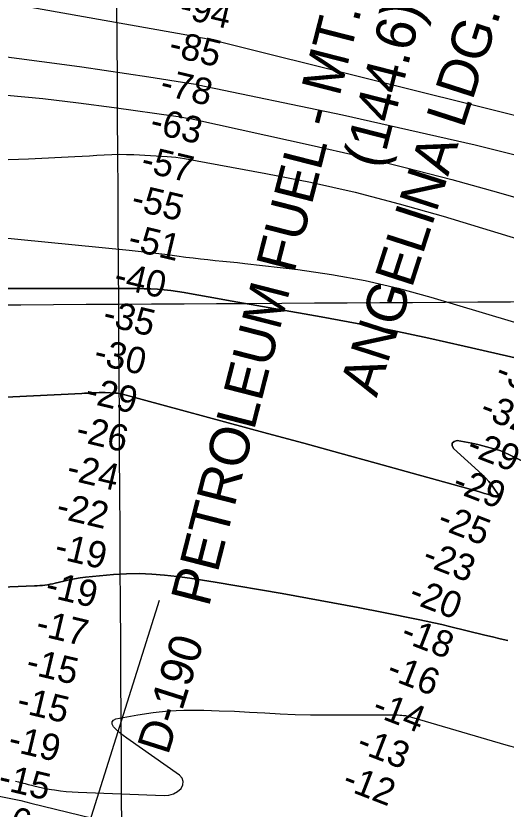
# Model space of a CAD drawing. Extents: x 3477039 to 3515015, y 546746 to 572297.
# Drawn here: x 3496761 to 3497998, y 563045 to 565048 of the extents above; entities that cross this region are included whole.
import ezdxf

# ---------------------------------------------------------------- set-up
doc = ezdxf.new("R2010")
doc.units = 0
for name, color, linetype in [('V-CHAN-NAID', 7, 'Continuous'), ('V-GRID-MAJR', 7, 'Continuous'), ('V-RIVR-RANG', 7, 'Continuous'), ('V-RIVR-RANG-IDEN', 7, 'Continuous'), ('V-TOPO-DPTH', 7, 'Continuous'), ('V-TOPO-GNAM-IDEN', 7, 'Continuous'), ('V-TOPO-MAJR', 7, 'Continuous'), ('V-TOPO-MINR', 7, 'Continuous')]:
    doc.layers.add(name, color=color, linetype=linetype)

msp = doc.modelspace()

# ---------------------------------------------------------------- linework, layer by layer
at = {"layer": 'V-GRID-MAJR'}
for points in [[(3497073.037565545, 555496.0515890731), (3497056.56, 558259.177), (3497020.416, 564320.132), (3496984.272, 570381.104), (3496984.251, 570384.554)], [(3481202.017, 564229.252), (3486474.821, 564258.778), (3491747.6210000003, 564289.072), (3497020.416, 564320.132), (3502293.207, 564351.96), (3507565.9930000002, 564384.554), (3512838.775, 564417.915)]]:
    msp.add_spline(points, degree=3, dxfattribs=at)
at = {"layer": 'V-RIVR-RANG'}
msp.add_line((3496858.6666, 562733.698), (3497123.1673, 563573.0069000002), dxfattribs=at)
at = {"layer": 'V-TOPO-DPTH'}
for points in [[(3496702.2082517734, 564359.3917912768), (3496786.063740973, 564359.4427881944), (3496869.919228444, 564359.4967588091), (3497051.3101174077, 564359.6183290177), (3497068.1567175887, 564359.4691649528), (3497084.996673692, 564359.1062361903), (3497101.8266636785, 564358.4226603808), (3497118.6500095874, 564357.5253198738), (3497135.4320060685, 564356.170667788), (3497152.1656604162, 564354.4213604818), (3497168.8268015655, 564352.0800703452), (3497185.4396005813, 564349.3441249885), (3497199.1042991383, 564346.8440532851), (3497222.5170422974, 564342.5832363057), (3497245.9350614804, 564338.351775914), (3497269.3609946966, 564334.1643504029), (3497292.7922039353, 564330.0062814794), (3497531.493061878, 564287.8781829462), (3497622.125860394, 564271.1326110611), (3497712.5617484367, 564253.4225573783), (3497802.7022707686, 564234.265780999), (3497892.645882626, 564214.1445228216), (3498028.15102787, 564182.6885954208)], [(3498028.15102787, 564182.6885954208), (3497892.645882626, 564214.1445228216), (3497802.7022707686, 564234.265780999), (3497712.5617484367, 564253.4225573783), (3497622.125860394, 564271.1326110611), (3497531.493061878, 564287.8781829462), (3497292.7922039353, 564330.0062814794), (3497269.3609946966, 564334.1643504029), (3497245.9350614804, 564338.351775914), (3497222.5170422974, 564342.5832363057), (3497199.1042991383, 564346.8440532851), (3497185.4396005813, 564349.3441249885), (3497168.8268015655, 564352.0800703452), (3497152.1656604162, 564354.4213604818), (3497135.4320060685, 564356.170667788), (3497118.6500095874, 564357.5253198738), (3497101.8266636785, 564358.4226603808), (3497084.996673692, 564359.1062361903), (3497068.1567175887, 564359.4691649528), (3497051.3101174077, 564359.6183290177), (3496869.919228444, 564359.4967588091), (3496786.063740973, 564359.4427881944), (3496702.2082517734, 564359.3917912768)], [(3496682.648173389, 564083.0086380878), (3496926.9095199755, 564094.6061176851), (3496934.297223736, 564094.9736675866), (3496941.6836987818, 564095.3635357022), (3496949.068330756, 564095.7868811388), (3496956.4517340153, 564096.2325447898), (3496963.8356742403, 564096.5856461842), (3496971.2215552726, 564096.7933057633), (3496978.610347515, 564096.7828026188), (3496986.001080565, 564096.6268576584), (3497012.538516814, 564095.6746411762), (3497016.9247466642, 564095.3660759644), (3497021.280975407, 564094.8591976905), (3497025.5922024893, 564094.0548498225), (3497029.873428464, 564093.0521888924), (3497396.2161167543, 563993.8614625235), (3497487.5405047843, 563969.0158873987), (3497578.8243943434, 563944.0230949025), (3497670.047536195, 563918.8094763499), (3497761.2301795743, 563893.4486404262), (3497928.218583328, 563846.786023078), (3497935.868042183, 563844.6167320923), (3497943.5060247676, 563842.4083141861), (3497951.1267929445, 563840.1412058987), (3497958.7360848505, 563837.8349706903), (3497969.531241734, 563834.5177690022), (3497971.7475437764, 563833.9044253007), (3497973.9813136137, 563833.3753167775), (3497978.518724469, 563832.6540404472), (3497979.7706447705, 563833.034006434), (3497980.598348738, 563833.6732466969), (3497980.789728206, 563834.7013983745), (3497980.5568913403, 563835.9888243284), (3497969.17878619, 563853.1896982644), (3497962.0737511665, 563863.1009553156), (3497954.5078858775, 563872.6167491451), (3497946.2507751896, 563881.5393481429), (3497937.532834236, 563890.0664839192), (3497865.0312539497, 563955.8407342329), (3497862.2254753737, 563963.2474171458), (3497862.3658845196, 563969.2603234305), (3497866.925575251, 563973.1825647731), (3497874.431453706, 563975.7110294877), (3497893.0607242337, 563972.5935193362), (3497911.5913795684, 563969.0126805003), (3497929.974112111, 563964.7368486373), (3497948.2582294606, 563959.9976880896), (3497979.4528381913, 563951.2820016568), (3497982.36154546, 563950.3874097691), (3497985.233414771, 563949.3945763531), (3497988.0500271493, 563948.2543806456), (3497990.82980157, 563947.0159434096), (3498512.3754094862, 563698.2603883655)], [(3498512.3754094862, 563698.2603883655), (3497990.82980157, 563947.0159434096), (3497988.0500271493, 563948.2543806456), (3497985.233414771, 563949.3945763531), (3497982.36154546, 563950.3874097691), (3497979.4528381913, 563951.2820016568), (3497948.2582294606, 563959.9976880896), (3497929.974112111, 563964.7368486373), (3497911.5913795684, 563969.0126805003), (3497893.0607242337, 563972.5935193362), (3497874.431453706, 563975.7110294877), (3497866.925575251, 563973.1825647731), (3497862.3658845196, 563969.2603234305), (3497862.2254753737, 563963.2474171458), (3497865.0312539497, 563955.8407342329), (3497937.532834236, 563890.0664839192), (3497946.2507751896, 563881.5393481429), (3497954.5078858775, 563872.6167491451), (3497962.0737511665, 563863.1009553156), (3497969.17878619, 563853.1896982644), (3497980.5568913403, 563835.9888243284), (3497980.789728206, 563834.7013983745), (3497980.598348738, 563833.6732466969), (3497979.7706447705, 563833.034006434), (3497978.518724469, 563832.6540404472), (3497973.9813136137, 563833.3753167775), (3497971.7475437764, 563833.9044253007), (3497969.531241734, 563834.5177690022), (3497958.7360848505, 563837.8349706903), (3497951.1267929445, 563840.1412058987), (3497943.5060247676, 563842.4083141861), (3497935.868042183, 563844.6167320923), (3497928.218583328, 563846.786023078), (3497761.2301795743, 563893.4486404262), (3497670.047536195, 563918.8094763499), (3497578.8243943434, 563944.0230949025), (3497487.5405047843, 563969.0158873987), (3497396.2161167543, 563993.8614625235), (3497029.873428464, 564093.0521888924), (3497025.5922024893, 564094.0548498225), (3497021.280975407, 564094.8591976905), (3497016.9247466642, 564095.3660759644), (3497012.538516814, 564095.6746411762), (3496986.001080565, 564096.6268576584), (3496978.610347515, 564096.7828026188), (3496971.2215552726, 564096.7933057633), (3496963.8356742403, 564096.5856461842), (3496956.4517340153, 564096.2325447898), (3496949.068330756, 564095.7868811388), (3496941.6836987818, 564095.3635357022), (3496934.297223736, 564094.9736675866), (3496926.9095199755, 564094.6061176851), (3496682.648173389, 564083.0086380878)], [(3498002.228981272, 563471.02758094), (3497983.099634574, 563475.6016861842), (3497963.9761578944, 563480.2002711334), (3497944.85659456, 563484.8151758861), (3497855.612866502, 563506.4164557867), (3497835.861812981, 563511.0774207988), (3497816.077147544, 563515.5869153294), (3497796.242064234, 563519.8692041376), (3497776.3733690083, 563524.0000224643), (3497688.7559025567, 563541.6926317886), (3497624.999183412, 563554.2657245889), (3497561.170379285, 563566.4517011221), (3497497.233447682, 563578.0570032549), (3497433.2244310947, 563589.2751891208), (3497263.4964403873, 563618.22715432), (3497231.6693679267, 563623.3745236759), (3497199.790560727, 563628.1554442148), (3497167.8341514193, 563632.3866915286), (3497135.8260073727, 563636.2514900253), (3497103.770887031, 563638.8360883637), (3497071.70499835, 563640.0923518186), (3497039.622957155, 563639.3561129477), (3497007.5301476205, 563637.2915391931), (3496936.5476980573, 563630.5036335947), (3496922.6929846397, 563628.8677120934), (3496908.9076787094, 563626.8256128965), (3496895.2264840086, 563624.1742471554), (3496881.6146967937, 563621.1167037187), (3496860.419542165, 563615.8590361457), (3496853.932455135, 563614.3675956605), (3496847.4172268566, 563613.0257411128), (3496840.859786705, 563611.9082654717), (3496834.2742053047, 563610.9403757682), (3496827.6599558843, 563610.1740204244), (3496821.035717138, 563609.5261859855), (3496814.396494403, 563609.0561329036), (3496807.7472823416, 563608.7046007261), (3496641.274971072, 563602.1401168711)], [(3498002.228981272, 563471.02758094), (3497983.099634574, 563475.6016861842), (3497963.9761578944, 563480.2002711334), (3497944.85659456, 563484.8151758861), (3497855.612866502, 563506.4164557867), (3497835.861812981, 563511.0774207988), (3497816.077147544, 563515.5869153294), (3497796.242064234, 563519.8692041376), (3497776.3733690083, 563524.0000224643), (3497688.7559025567, 563541.6926317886), (3497624.999183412, 563554.2657245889), (3497561.170379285, 563566.4517011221), (3497497.233447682, 563578.0570032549), (3497433.2244310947, 563589.2751891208), (3497263.4964403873, 563618.22715432), (3497231.6693679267, 563623.3745236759), (3497199.790560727, 563628.1554442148), (3497167.8341514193, 563632.3866915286), (3497135.8260073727, 563636.2514900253), (3497103.770887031, 563638.8360883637), (3497071.70499835, 563640.0923518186), (3497039.622957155, 563639.3561129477), (3497007.5301476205, 563637.2915391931), (3496936.5476980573, 563630.5036335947), (3496922.6929846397, 563628.8677120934), (3496908.9076787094, 563626.8256128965), (3496895.2264840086, 563624.1742471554), (3496881.6146967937, 563621.1167037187), (3496860.419542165, 563615.8590361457), (3496853.932455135, 563614.3675956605), (3496847.4172268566, 563613.0257411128), (3496840.859786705, 563611.9082654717), (3496834.2742053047, 563610.9403757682), (3496827.6599558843, 563610.1740204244), (3496821.035717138, 563609.5261859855), (3496814.396494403, 563609.0561329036), (3496807.7472823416, 563608.7046007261), (3496641.274971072, 563602.1401168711)], [(3493229.878468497, 563072.8204755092), (3493252.4904955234, 563075.280705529), (3493820.521116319, 563141.1998917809), (3493878.2458697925, 563147.9396933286), (3493935.969263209, 563154.6911079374), (3493993.690616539, 563161.4599421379), (3494051.410609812, 563168.2403893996), (3494098.9143100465, 563173.8279815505), (3494132.8848558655, 563177.7934906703), (3494166.85996526, 563181.7191975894), (3494200.841920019, 563185.5852012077), (3494234.828438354, 563189.4114026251), (3495006.711404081, 563256.7537761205), (3495030.941599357, 563258.410372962), (3495055.1861756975, 563259.7508219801), (3495079.4523236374, 563260.617049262), (3495923.062161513, 563231.598491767), (3495938.765666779, 563230.3151384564), (3495954.4342274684, 563228.7300263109), (3495970.0503712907, 563226.6922759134), (3495985.631570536, 563224.3527666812), (3496773.57259656, 563066.7548253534), (3496798.264202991, 563060.3077159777), (3497514.3571759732, 562885.9203614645)], [(3493229.878468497, 563072.8204755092), (3493252.4904955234, 563075.280705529), (3493820.521116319, 563141.1998917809), (3493878.2458697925, 563147.9396933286), (3493935.969263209, 563154.6911079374), (3493993.690616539, 563161.4599421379), (3494051.410609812, 563168.2403893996), (3494098.9143100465, 563173.8279815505), (3494132.8848558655, 563177.7934906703), (3494166.85996526, 563181.7191975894), (3494200.841920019, 563185.5852012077), (3494234.828438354, 563189.4114026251), (3495006.711404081, 563256.7537761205), (3495030.941599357, 563258.410372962), (3495055.1861756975, 563259.7508219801), (3495079.4523236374, 563260.617049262), (3495923.062161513, 563231.598491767), (3495938.765666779, 563230.3151384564), (3495954.4342274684, 563228.7300263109), (3495970.0503712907, 563226.6922759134), (3495985.631570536, 563224.3527666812), (3496773.57259656, 563066.7548253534), (3496798.264202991, 563060.3077159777), (3497514.3571759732, 562885.9203614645)]]:
    msp.add_lwpolyline(points, dxfattribs=at)
at = {"layer": 'V-TOPO-MAJR'}
msp.add_lwpolyline([(3496628.301840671, 564497.627744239), (3497046.651666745, 564456.1750465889), (3497076.722682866, 564453.0324706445), (3497106.768539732, 564449.67517482), (3497136.776657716, 564445.9957991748), (3497166.759616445, 564442.101703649), (3497189.3796501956, 564439.0404296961), (3497208.0471936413, 564436.6341726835), (3497226.732698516, 564434.3855697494), (3497245.4451455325, 564432.373447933), (3497264.1755539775, 564430.5189801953), (3497282.9127010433, 564428.7181656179), (3497301.64086585, 564426.8311856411), (3497320.3555572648, 564424.814957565), (3497339.0612664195, 564422.7125640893), (3497472.6556469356, 564407.2303054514), (3497557.691164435, 564395.0888185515), (3497642.11644291, 564379.9887226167), (3497725.6263628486, 564360.4507131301), (3497808.5260437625, 564337.9540946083), (3498075.3191405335, 564257.9218597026)], dxfattribs=at)
at = {"layer": 'V-TOPO-MINR'}
for points in [[(3496342.3812597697, 565151.3465412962), (3497206.9236623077, 564997.144698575), (3497222.0827686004, 564994.337410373), (3497237.21509143, 564991.3969899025), (3497252.307239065, 564988.2568710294), (3497267.3726032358, 564984.9836198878), (3498025.666166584, 564795.1488718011)], [(3495949.707282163, 565076.7906722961), (3496086.0752054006, 565039.151492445), (3496117.886138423, 565031.0781049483), (3496149.8774097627, 565023.8936093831), (3496182.1391885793, 565018.0424517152), (3496214.581305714, 565013.0801859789), (3496870.986898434, 564926.5827166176), (3496927.5048720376, 564918.9208100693), (3496983.982357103, 564910.9785647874), (3497040.3991093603, 564902.6158114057), (3497096.7753730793, 564893.9727192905), (3497197.5417736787, 564878.139754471), (3497203.4964675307, 564877.1590184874), (3497209.4405010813, 564876.1198517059), (3497215.368544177, 564874.9930387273), (3497221.2859269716, 564873.807794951), (3497584.8779848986, 564798.184509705), (3497920.258296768, 564722.1789611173), (3498031.489759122, 564694.4248740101)], [(3495608.9450934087, 565002.0649151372), (3495660.0320064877, 564988.9418284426), (3495711.4708122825, 564977.0892904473), (3496130.9073265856, 564888.6931176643), (3496131.278937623, 564888.6145444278), (3496133.136023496, 564888.2171264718), (3496135.821669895, 564887.814793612), (3496139.8405853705, 564887.6610861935), (3496647.7262434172, 564854.3819178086), (3496738.300405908, 564847.4010249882), (3496828.730545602, 564839.0365684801), (3496918.9446511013, 564828.5967664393), (3497009.0147338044, 564816.7734007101), (3497164.7665417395, 564794.5047865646), (3497176.828314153, 564792.6428415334), (3497188.857780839, 564790.602508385), (3497200.838788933, 564788.2945930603), (3497212.7874912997, 564785.8082896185), (3497506.264825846, 564721.3202975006), (3497625.110973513, 564694.0356873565), (3497743.5840548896, 564665.2747894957), (3497861.4975368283, 564634.2994600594), (3497979.037952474, 564601.847842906), (3498180.754955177, 564544.1167641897)], [(3496715.5798898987, 564684.443326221), (3496792.6444455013, 564686.776020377), (3496909.5292812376, 564692.6262022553), (3496928.1725346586, 564693.6093338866), (3496946.8118650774, 564694.6589600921), (3496965.4453109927, 564695.8083281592), (3496984.0748339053, 564697.0241908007), (3497002.7035873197, 564697.944622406), (3497021.335228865, 564698.4060984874), (3497039.971202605, 564698.179141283), (3497058.6100644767, 564697.4932285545), (3497142.8833383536, 564692.8312493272), (3497153.9090315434, 564692.0129603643), (3497164.90212898, 564690.919582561), (3497175.846332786, 564689.413571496), (3497186.7579408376, 564687.6324715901), (3497391.669243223, 564650.213558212), (3497504.550335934, 564627.6076672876), (3497616.8175575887, 564602.4641355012), (3497728.163972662, 564573.5141424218), (3497838.8965166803, 564542.0265084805), (3498145.696839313, 564449.1108297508)], [(3496702.2082517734, 564359.3917912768), (3496786.063740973, 564359.4427881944), (3496869.919228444, 564359.4967588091), (3497051.3101174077, 564359.6183290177), (3497068.1567175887, 564359.4691649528), (3497084.996673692, 564359.1062361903), (3497101.8266636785, 564358.4226603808), (3497118.6500095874, 564357.5253198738), (3497135.4320060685, 564356.170667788), (3497152.1656604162, 564354.4213604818), (3497168.8268015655, 564352.0800703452), (3497185.4396005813, 564349.3441249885), (3497199.1042991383, 564346.8440532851), (3497222.5170422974, 564342.5832363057), (3497245.9350614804, 564338.351775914), (3497269.3609946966, 564334.1643504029), (3497292.7922039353, 564330.0062814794), (3497531.493061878, 564287.8781829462), (3497622.125860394, 564271.1326110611), (3497712.5617484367, 564253.4225573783), (3497802.7022707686, 564234.265780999), (3497892.645882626, 564214.1445228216), (3498028.15102787, 564182.6885954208)], [(3496682.648173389, 564083.0086380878), (3496926.9095199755, 564094.6061176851), (3496934.297223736, 564094.9736675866), (3496941.6836987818, 564095.3635357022), (3496949.068330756, 564095.7868811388), (3496956.4517340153, 564096.2325447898), (3496963.8356742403, 564096.5856461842), (3496971.2215552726, 564096.7933057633), (3496978.610347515, 564096.7828026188), (3496986.001080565, 564096.6268576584), (3497012.538516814, 564095.6746411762), (3497016.9247466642, 564095.3660759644), (3497021.280975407, 564094.8591976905), (3497025.5922024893, 564094.0548498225), (3497029.873428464, 564093.0521888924), (3497396.2161167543, 563993.8614625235), (3497487.5405047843, 563969.0158873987), (3497578.8243943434, 563944.0230949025), (3497670.047536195, 563918.8094763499), (3497761.2301795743, 563893.4486404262), (3497928.218583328, 563846.786023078), (3497935.868042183, 563844.6167320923), (3497943.5060247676, 563842.4083141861), (3497951.1267929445, 563840.1412058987), (3497958.7360848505, 563837.8349706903), (3497969.531241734, 563834.5177690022), (3497971.7475437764, 563833.9044253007), (3497973.9813136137, 563833.3753167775), (3497978.518724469, 563832.6540404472), (3497979.7706447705, 563833.034006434), (3497980.598348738, 563833.6732466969), (3497980.789728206, 563834.7013983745), (3497980.5568913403, 563835.9888243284), (3497969.17878619, 563853.1896982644), (3497962.0737511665, 563863.1009553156), (3497954.5078858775, 563872.6167491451), (3497946.2507751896, 563881.5393481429), (3497937.532834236, 563890.0664839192), (3497865.0312539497, 563955.8407342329), (3497862.2254753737, 563963.2474171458), (3497862.3658845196, 563969.2603234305), (3497866.925575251, 563973.1825647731), (3497874.431453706, 563975.7110294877), (3497893.0607242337, 563972.5935193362), (3497911.5913795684, 563969.0126805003), (3497929.974112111, 563964.7368486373), (3497948.2582294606, 563959.9976880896), (3497979.4528381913, 563951.2820016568), (3497982.36154546, 563950.3874097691), (3497985.233414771, 563949.3945763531), (3497988.0500271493, 563948.2543806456), (3497990.82980157, 563947.0159434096), (3498512.3754094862, 563698.2603883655)], [(3496641.274971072, 563602.1401168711), (3496807.7472823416, 563608.7046007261), (3496814.396494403, 563609.0561329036), (3496821.035717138, 563609.5261859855), (3496827.6599558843, 563610.1740204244), (3496834.2742053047, 563610.9403757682), (3496840.859786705, 563611.9082654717), (3496847.4172268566, 563613.0257411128), (3496853.932455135, 563614.3675956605), (3496860.419542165, 563615.8590361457), (3496881.6146967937, 563621.1167037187), (3496895.2264840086, 563624.1742471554), (3496908.9076787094, 563626.8256128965), (3496922.6929846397, 563628.8677120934), (3496936.5476980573, 563630.5036335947), (3497007.5301476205, 563637.2915391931), (3497039.622957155, 563639.3561129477), (3497071.70499835, 563640.0923518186), (3497103.770887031, 563638.8360883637), (3497135.8260073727, 563636.2514900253), (3497167.8341514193, 563632.3866915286), (3497199.790560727, 563628.1554442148), (3497231.6693679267, 563623.3745236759), (3497263.4964403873, 563618.22715432), (3497433.2244310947, 563589.2751891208), (3497497.233447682, 563578.0570032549), (3497561.170379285, 563566.4517011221), (3497624.999183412, 563554.2657245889), (3497688.7559025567, 563541.6926317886), (3497776.3733690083, 563524.0000224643), (3497796.242064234, 563519.8692041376), (3497816.077147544, 563515.5869153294), (3497835.861812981, 563511.0774207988), (3497855.612866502, 563506.4164557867), (3497944.85659456, 563484.8151758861), (3497963.9761578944, 563480.2002711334), (3497983.099634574, 563475.6016861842), (3498002.228981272, 563471.02758094)], [(3496759.6058951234, 563115.8150519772), (3496767.7329699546, 563113.8756605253), (3496775.8367659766, 563111.8269171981), (3496783.9373027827, 563109.7654298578), (3496792.0329507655, 563107.684826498), (3496800.125339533, 563105.5914791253), (3496805.9557200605, 563104.0759261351), (3496816.9970825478, 563101.3928263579), (3496828.086635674, 563098.9459478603), (3496839.2484747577, 563096.8534012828), (3496850.45850448, 563094.9970759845), (3496858.0165890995, 563093.868871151), (3496873.065177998, 563091.8742952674), (3496888.1447416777, 563090.2099228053), (3496903.270767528, 563089.0408554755), (3496918.42776816, 563088.2019915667), (3497135.2613618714, 563079.7660072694), (3497147.3073290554, 563080.9453542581), (3497158.5478065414, 563084.0258784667), (3497168.5800494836, 563089.958168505), (3497177.8068027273, 563097.7916357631), (3497182.1313811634, 563106.8153987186), (3497183.428402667, 563115.4886708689), (3497180.184088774, 563123.6362068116), (3497173.9122179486, 563131.4332519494), (3497040.859936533, 563224.4024852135), (3497031.8556491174, 563231.0940366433), (3497023.134396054, 563238.1168043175), (3497014.8376945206, 563245.636396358), (3497006.82402734, 563253.4872046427), (3497004.232116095, 563259.8957974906), (3497004.05628843, 563265.5191365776), (3497007.504586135, 563269.9645950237), (3497013.36896742, 563273.6247997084), (3497068.5025648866, 563283.4224644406), (3497107.230980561, 563289.1025477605), (3497146.0776404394, 563293.2141081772), (3497185.1016666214, 563294.9728842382), (3497224.243937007, 563295.1631373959), (3497235.2287943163, 563294.8842276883), (3497273.737923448, 563293.6968971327), (3497312.234903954, 563292.2305260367), (3497350.713661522, 563290.3455941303), (3497389.180270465, 563288.1816216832), (3497427.648741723, 563286.1578130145), (3497466.1318368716, 563284.5996513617), (3497504.636867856, 563283.7399602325), (3497543.1565227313, 563283.345916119), (3497715.983753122, 563283.1461223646), (3497720.6606193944, 563283.0836530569), (3497725.3343072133, 563282.9452085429), (3497730.003227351, 563282.692801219), (3497734.6689690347, 563282.3644186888), (3497738.8309102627, 563282.0204197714), (3497741.4006935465, 563281.7357734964), (3497743.953795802, 563281.3568667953), (3497746.4818765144, 563280.8365694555), (3497748.9932762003, 563280.2220116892), (3497751.4902100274, 563279.5296808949), (3497753.984657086, 563278.8285909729), (3497756.475373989, 563278.1143623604), (3497758.963604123, 563277.3913746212), (3497997.71047477, 563207.3374701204), (3498028.3158173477, 563199.0029003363)], [(3493229.878468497, 563072.8204755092), (3493252.4904955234, 563075.280705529), (3493820.521116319, 563141.1998917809), (3493878.2458697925, 563147.9396933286), (3493935.969263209, 563154.6911079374), (3493993.690616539, 563161.4599421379), (3494051.410609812, 563168.2403893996), (3494098.9143100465, 563173.8279815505), (3494132.8848558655, 563177.7934906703), (3494166.85996526, 563181.7191975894), (3494200.841920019, 563185.5852012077), (3494234.828438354, 563189.4114026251), (3495006.711404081, 563256.7537761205), (3495030.941599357, 563258.410372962), (3495055.1861756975, 563259.7508219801), (3495079.4523236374, 563260.617049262), (3495923.062161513, 563231.598491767), (3495938.765666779, 563230.3151384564), (3495954.4342274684, 563228.7300263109), (3495970.0503712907, 563226.6922759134), (3495985.631570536, 563224.3527666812), (3496773.57259656, 563066.7548253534), (3496798.264202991, 563060.3077159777), (3497514.3571759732, 562885.9203614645)]]:
    msp.add_lwpolyline(points, dxfattribs=at)

# ---------------------------------------------------------------- texts
at = {"layer": 'V-CHAN-NAID'}
for s, p in [('PETROLEUM FUEL - MT. AIRY ', (3497247.648741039, 563553.2107942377)), (' (144.6) (2)', (3497674.3394934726, 564623.0403893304))]:
    msp.add_text(s, height=100.000002, rotation=75.65544141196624, dxfattribs=at).set_placement(p)
at = {"layer": 'V-RIVR-RANG'}
for s, height, rotation, p in [('-94', 67.00000000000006, 346.5977222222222, (3497169.760754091, 565044.4779205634)), ('-85', 67.00000000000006, 346.5977222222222, (3497143.51919885, 564947.931466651)), ('-78', 67.00000000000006, 346.5977222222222, (3497121.639774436, 564850.3456233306)), ('-63', 67.00000000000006, 346.5977222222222, (3497096.168006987, 564753.615747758)), ('-57', 67.00000000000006, 346.5977222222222, (3497073.5073054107, 564656.2160637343)), ('-55', 67.00000000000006, 346.5977222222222, (3497048.8168151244, 564559.3000288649)), ('-51', 67.00000000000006, 346.5977222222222, (3497040.5359750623, 564458.4737362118)), ('-40', 67.00000000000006, 346.5977222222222, (3497004.8003703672, 564364.1894827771)), ('-35', 67.00000000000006, 346.5977222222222, (3496977.0192395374, 564268.0098721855)), ('-30', 67.00000000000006, 346.5977222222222, (3496954.370027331, 564170.607450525)), ('-34', 67.00000000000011, 338.8322777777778, (3497967.44186847, 564128.5780185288)), ('-29', 67.00000000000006, 346.5977222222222, (3496932.490602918, 564073.0216072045)), ('-32', 67.00000000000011, 338.8322777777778, (3497928.396070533, 564036.461775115)), ('-26', 67.00000000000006, 346.5977222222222, (3496908.8150069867, 563975.863747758)), ('-29', 67.00000000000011, 338.8322777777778, (3497895.252831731, 563942.0605173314)), ('-24', 67.00000000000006, 346.5977222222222, (3496885.6526029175, 563878.5836072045)), ('-29', 67.00000000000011, 338.8322777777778, (3497858.912831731, 563848.8975173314)), ('-22', 67.00000000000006, 346.5977222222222, (3496859.411047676, 563782.0371532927)), ('-25', 67.00000000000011, 338.8322777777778, (3497820.849960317, 563756.4012715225)), ('-19', 67.00000000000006, 346.5977222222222, (3496855.236742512, 563680.2326117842)), ('-23', 67.00000000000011, 338.8322777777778, (3497783.0340705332, 563663.809775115)), ('-19', 67.00000000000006, 346.5977222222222, (3496831.8177425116, 563583.0136117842)), ('-20', 67.00000000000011, 338.8322777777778, (3497748.9069052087, 563569.7895197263)), ('-17', 67.00000000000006, 346.5977222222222, (3496807.8730612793, 563485.919630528)), ('-18', 67.00000000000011, 338.8322777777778, (3497728.555711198, 563470.4352308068)), ('-15', 67.00000000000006, 346.5977222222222, (3496783.1825709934, 563389.0025956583)), ('-16', 67.00000000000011, 338.8322777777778, (3497692.7076744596, 563377.0807296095)), ('-15', 67.00000000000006, 346.5977222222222, (3496759.7635709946, 563291.7835956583)), ('-14', 67.00000000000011, 338.8322777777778, (3497656.6126560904, 563283.8224790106)), ('-19', 67.00000000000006, 346.5977222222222, (3496738.140742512, 563194.1366117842)), ('-13', 67.00000000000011, 338.8322777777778, (3497617.0748948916, 563191.8977367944)), ('-15', 67.00000000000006, 346.5977222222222, (3496712.9255709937, 563097.3455956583)), ('-12', 67.00000000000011, 338.8322777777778, (3497581.2258581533, 563098.5442355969)), ('0.6', 67.00000000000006, 346.5977222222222, (3496668.9788965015, 563005.0178399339))]:
    msp.add_text(s, height=height, rotation=rotation, dxfattribs=at).set_placement(p)
at = {"layer": 'V-RIVR-RANG-IDEN'}
msp.add_text('D-190', height=83, rotation=72.36632571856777, dxfattribs=at).set_placement((3497144.7515258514, 563180.0742401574))
at = {"layer": 'V-TOPO-GNAM-IDEN'}
msp.add_text('ANGELINA LDG.', height=99.99980199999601, rotation=72.12067506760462, dxfattribs=at).set_placement((3497671.112759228, 564082.4117854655))

doc.saveas('drawing.dxf')
